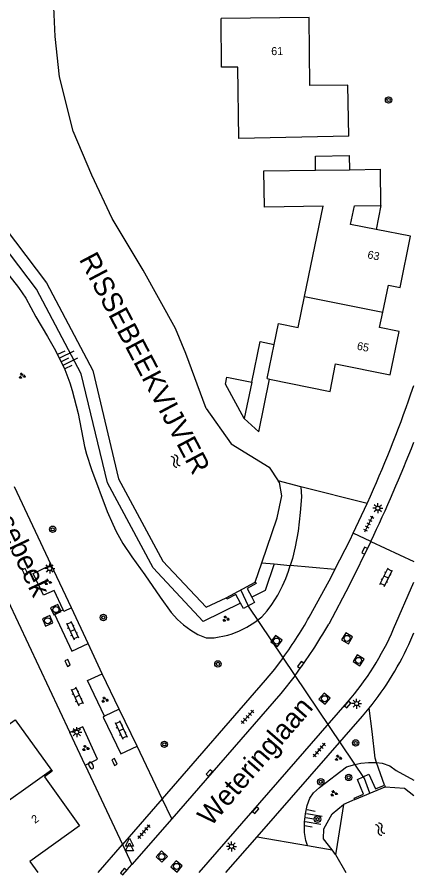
# Model space of a CAD drawing. Extents: x 128999 to 131010, y 395498 to 399007.
# Drawn here: x 130950.5 to 131000, y 395499.7 to 395606.9 of the extents above; entities that cross this region are included whole.
import ezdxf

# ---------------------------------------------------------------- set-up
doc = ezdxf.new("R2010")
doc.units = 0
for name, color, linetype in [('gg-afsc-erfafscheiding', 7, 'Continuous'), ('gg-anno-huisnummerreeks BGT', 7, 'Continuous'), ('gg-anno-naam water', 7, 'Continuous'), ('gg-anno-openbare ruimte label', 7, 'Continuous'), ('gg-bbg-gedigitaliseerde bebouwing', 7, 'Continuous'), ('gg-bbg-gedigitaliseerde bijgebouw', 7, 'Continuous'), ('gg-bbg-hoofdgebouw', 7, 'Continuous'), ('gg-bbg-luifel en loopbrug', 7, 'Continuous'), ('gg-bbg-tussenscheiding', 7, 'Continuous'), ('gg-knt-BGT kruinlijn', 7, 'Continuous'), ('gg-knt-verharding', 7, 'Continuous'), ('gg-knt-verharding nz', 7, 'Continuous'), ('gg-kntw-beschoeiing', 7, 'Continuous'), ('gg-kwrk-duiker nz buis', 7, 'Continuous'), ('gg-kwrk-uitstroombak niveau min 01', 7, 'Continuous'), ('gt-grn-groengrens', 7, 'Continuous'), ('gt-grn-vlakafsluiter', 7, 'Continuous'), ('gt-grn-weggrens', 7, 'Continuous'), ('gt-symb-boom', 7, 'Continuous'), ('gt-symb-brandkraan', 7, 'Continuous'), ('gt-symb-groenvak', 7, 'Continuous'), ('gt-symb-klinker verharding', 7, 'Continuous'), ('gt-symb-kolk', 7, 'Continuous'), ('gt-symb-lichtmast', 7, 'Continuous'), ('gt-symb-rioolschacht', 7, 'Continuous'), ('gt-symb-talud symbool', 7, 'Continuous'), ('gt-symb-tegel verharding', 7, 'Continuous'), ('gt-symb-waterafsluiter', 7, 'Continuous'), ('gt-symb-watersymbool', 7, 'Continuous')]:
    doc.layers.add(name, color=color, linetype=linetype)

# ---------------------------------------------------------------- blocks, each defined once
blk = doc.blocks.new('gt0-KL1')
at = {"layer": 'gt-symb-klinker verharding'}
for p, q in [((-1.15, 0.3), (1.15, 0.3)), ((-1, -0.3), (-1, 0.3)), ((-0.5, 0.3), (-0.5, 0.45)), ((0, -0.3), (0, 0.3)), ((0.5, 0.3), (0.5, 0.45)), ((1, -0.3), (1, 0.3)), ((-1.15, -0.3), (1.15, -0.3)), ((-0.5, -0.45), (-0.5, -0.3)), ((0.5, -0.45), (0.5, -0.3))]:
    blk.add_line(p, q, dxfattribs=at)
blk = doc.blocks.new('gt0-KOLK')
at = {"layer": 'gt-symb-kolk'}
blk.add_lwpolyline([(0, 0), (0.38, 0), (0.38, 0.4), (-0.38, 0.4), (-0.38, 0), (0, 0)], dxfattribs=at)
blk = doc.blocks.new('gt0-TEG1')
at = {"layer": 'gt-symb-tegel verharding'}
for p, q in [((-1.12, 0), (1.12, 0)), ((-0.9, -0.25), (-0.9, 0.25)), ((-0.45, -0.25), (-0.45, 0.25)), ((0, -0.25), (0, 0.25)), ((0.45, -0.25), (0.45, 0.25)), ((0.9, -0.25), (0.9, 0.25))]:
    blk.add_line(p, q, dxfattribs=at)
blk = doc.blocks.new('gt0-LMAST')
at = {"layer": 'gt-symb-lichtmast'}
for p, q in [((-0.18, 0.17), (-0.45, 0.44)), ((-0.01, 0.25), (-0.01, 0.62)), ((0.17, 0.17), (0.44, 0.44)), ((-0.26, 0), (-0.63, 0)), ((-0.18, -0.18), (-0.45, -0.45)), ((-0.01, -0.25), (-0.01, -0.63)), ((0.44, -0.45), (0.17, -0.18)), ((0.24, 0), (0.62, 0))]:
    blk.add_line(p, q, dxfattribs=at)
blk.add_circle((-0.01, 0), 0.25, dxfattribs=at)
blk = doc.blocks.new('gt0-RS')
at = {"layer": 'gt-symb-rioolschacht'}
blk.add_lwpolyline([(-0.5, -0.5), (0.5, -0.5), (0.5, 0.5), (-0.5, 0.5)], close=True, dxfattribs=at)
blk.add_circle((0, 0), 0.375, dxfattribs=at)
blk = doc.blocks.new('gt0-BOOM')
at = {"layer": 'gt-symb-boom'}
for radius in [0.4, 0.2]:
    blk.add_circle((0, 0), radius, dxfattribs=at)
blk = doc.blocks.new('gt0-GRVAK')
at = {"layer": 'gt-symb-groenvak'}
for p, q in [((-0.11, 0.19), (-0.23, 0.24)), ((-0.18, 0.15), (0.09, 0.15)), ((-0.09, 0.21), (-0.16, 0.32)), ((-0.05, 0.21), (-0.05, 0.39)), ((0, 0.21), (0.06, 0.32)), ((0.01, 0.19), (0.13, 0.24)), ((0.26, -0.05), (0.2, 0.06)), ((0.31, -0.05), (0.31, 0.13)), ((0.35, -0.05), (0.41, 0.06)), ((-0.24, -0.23), (-0.36, -0.18)), ((-0.32, -0.26), (-0.05, -0.26)), ((-0.23, -0.21), (-0.29, -0.1)), ((-0.18, -0.2), (-0.18, -0.02)), ((-0.14, -0.21), (-0.07, -0.1)), ((-0.12, -0.23), (0, -0.18)), ((0.24, -0.07), (0.12, -0.02)), ((0.17, -0.11), (0.44, -0.11)), ((0.37, -0.07), (0.49, -0.02))]:
    blk.add_line(p, q, dxfattribs=at)
blk = doc.blocks.new('gt0-WA')
at = {"layer": 'gt-symb-watersymbool'}
for centre, start, end in [((-0.32, 0.02), 28.0725, 151.9275), ((0.43, 0.42), 208.0725, 331.9275), ((-0.32, -0.43), 28.0725, 151.9275), ((0.43, -0.03), 208.0725, 331.9275)]:
    blk.add_arc(centre, 0.425, start, end, dxfattribs=at)
blk = doc.blocks.new('gt0-TALUD_1')
at = {"layer": 'gt-symb-talud symbool'}
for p, q in [((-1, -1), (-1, 0)), ((-0.5, -2), (-0.5, 0)), ((0, -1), (0, 0)), ((0.5, -2), (0.5, 0)), ((1, -1), (1, 0))]:
    blk.add_line(p, q, dxfattribs=at)
blk = doc.blocks.new('gt0-WAFSL')
at = {"layer": 'gt-symb-waterafsluiter'}
for p, q in [((-0.5, -0.33), (0, 0.67)), ((0, 0.67), (0.5, -0.33)), ((0.5, -0.33), (-0.5, -0.33))]:
    blk.add_line(p, q, dxfattribs=at)
blk = doc.blocks.new('gt0-BR')
at = {"layer": 'gt-symb-brandkraan'}
for centre, radius, start, end in [((-0.24, 0), 0.206, 107.5669, 252.4331), ((0.6, -2.66), 3, 106.892, 107.5669), ((0, -0.69), 0.938, 73.108, 106.892), ((-0.6, -2.66), 3, 72.4331, 73.108), ((0.24, 0), 0.206, 287.567, 72.4331), ((0.6, 2.66), 3, 252.4331, 253.108), ((0, 0.69), 0.938, 253.108, 286.8921), ((-0.6, 2.66), 3, 286.8921, 287.567)]:
    blk.add_arc(centre, radius, start, end, dxfattribs=at)

msp = doc.modelspace()

# ---------------------------------------------------------------- linework, layer by layer
at = {"layer": 'gg-afsc-erfafscheiding'}
for p, q in [((130985.92, 395548.21), (130983.09, 395548.94)), ((130994.16, 395546.1), (130985.92, 395548.21)), ((130996.35, 395510.91), (130995.36, 395513.76))]:
    msp.add_line(p, q, dxfattribs=at)
msp.add_lwpolyline([(130995.36, 395513.76), (130995.18, 395514.28), (130994.82, 395517.61)], dxfattribs=at)
at = {"layer": 'gg-bbg-gedigitaliseerde bebouwing'}
for p, q in [((130987.74, 395587.75), (130991.96, 395587.81)), ((130991.96, 395587.81), (130995.84, 395587.86)), ((130981.69, 395561.71), (130982.58, 395565.98))]:
    msp.add_line(p, q, dxfattribs=at)
for points in [[(130991.88, 395592), (130978.16, 395591.72), (130978.05, 395600.63), (130976.02, 395600.63), (130975.95, 395606.68)], [(130986.37, 395571.96), (130988.67, 395583.24), (130981.35, 395583.14), (130981.29, 395587.66), (130987.74, 395587.75)], [(130982.58, 395565.98), (130983.12, 395568.59), (130985.58, 395568.09), (130986.37, 395571.96)]]:
    msp.add_lwpolyline(points, dxfattribs=at)
at = {"layer": 'gg-bbg-gedigitaliseerde bijgebouw'}
for p, q in [((130978.85, 395556.73), (130976.48, 395561)), ((130979.77, 395561.26), (130978.85, 395556.73))]:
    msp.add_line(p, q, dxfattribs=at)
msp.add_lwpolyline([(130976.48, 395561), (130976.66, 395561.9), (130979.77, 395561.26)], dxfattribs=at)
at = {"layer": 'gg-bbg-hoofdgebouw'}
for p, q in [((130995.9, 395583.35), (130995.84, 395587.86)), ((130981.69, 395561.71), (130982, 395561.64)), ((130982, 395561.64), (130989.55, 395560.1)), ((130952.08, 395501.38), (130953.07, 395500))]:
    msp.add_line(p, q, dxfattribs=at)
for points in [[(130991.88, 395592), (130991.78, 395598.38), (130987.03, 395598.33), (130986.95, 395606.81), (130975.95, 395606.68)], [(130995.3, 395580.34), (130992.09, 395580.97), (130992.58, 395583.3), (130995.9, 395583.35)], [(130996.13, 395570.02), (130996.85, 395573.37), (130998.28, 395573.11), (130999.59, 395579.49), (130995.3, 395580.34)], [(130989.55, 395560.1), (130990.24, 395563.54), (130997.06, 395562.17), (130998.18, 395567.6), (130995.72, 395568.08), (130996.13, 395570.02)], [(130942.74, 395521.1), (130946.22, 395516.22), (130950.26, 395519.1), (130954.79, 395512.79)], [(130954.79, 395512.79), (130954.86, 395512.68), (130953.9, 395511.98), (130958.29, 395505.84), (130952.08, 395501.38)]]:
    msp.add_lwpolyline(points, dxfattribs=at)
at = {"layer": 'gg-bbg-luifel en loopbrug'}
msp.add_line((130995.9, 395583.35), (130995.3, 395580.34), dxfattribs=at)
for points in [[(130987.74, 395587.75), (130987.71, 395589.5), (130991.93, 395589.59), (130991.96, 395587.81)], [(130979.77, 395561.26), (130980.81, 395566.34), (130982.58, 395565.98)], [(130978.85, 395556.73), (130980.65, 395555.07), (130982, 395561.64)]]:
    msp.add_lwpolyline(points, dxfattribs=at)
at = {"layer": 'gg-bbg-tussenscheiding'}
msp.add_line((130986.37, 395571.96), (130996.13, 395570.02), dxfattribs=at)
msp.add_lwpolyline([(130954.79, 395512.79), (130946.49, 395506.89), (130946.39, 395507.02)], dxfattribs=at)
at = {"layer": 'gg-knt-BGT kruinlijn'}
msp.add_line((130997.81, 395512.75), (131000, 395511.53), dxfattribs=at)
for points in [[(130948.57, 395575.78), (130950.68, 395573.11), (130951.58, 395571.75), (130952.85, 395569.42), (130954.3, 395566.98), (130955.27, 395565.23), (130956.45, 395562.85), (130957.07, 395561.2), (130957.36, 395560.24), (130958.11, 395557.36), (130958.92, 395553.25), (130959.17, 395552.28), (130959.76, 395550.37), (130961.75, 395545.12), (130962.43, 395543.51), (130962.86, 395542.61), (130963.69, 395541.12), (130964.81, 395539.43), (130966.42, 395537.21), (130968.33, 395534.41), (130969.74, 395532.49), (130970.52, 395531.6), (130971.28, 395530.95), (130972.19, 395530.3), (130973.05, 395529.74), (130974.08, 395529.34), (130975.07, 395529.35), (130976.78, 395529.67), (130977.34, 395529.82), (130978.26, 395530.19), (130979.15, 395530.66), (130980.18, 395531.29), (130981.03, 395531.97), (130981.71, 395532.7), (130982.3, 395533.51), (130983.02, 395534.66), (130983.62, 395535.82), (130984.03, 395536.73), (130984.38, 395537.67), (130984.59, 395538.38)], [(130985.92, 395548.21), (130985.98, 395546.96), (130985.83, 395544.97), (130985.57, 395542.64), (130985.18, 395540.68), (130984.85, 395539.24), (130984.59, 395538.38)], [(130986.73, 395503.37), (130986.52, 395504.03), (130986.35, 395505.02), (130986.36, 395506.33), (130986.47, 395507.33), (130986.67, 395508.37), (130987.01, 395509.29), (130987.48, 395509.95), (130988.21, 395510.63), (130991.58, 395513.21), (130992.64, 395513.52), (130993.4, 395513.68), (130994.33, 395513.77), (130995.36, 395513.76)], [(130995.36, 395513.76), (130996.06, 395513.68), (130997.02, 395513.36), (130997.81, 395512.75)]]:
    msp.add_lwpolyline(points, dxfattribs=at)
at = {"layer": 'gg-knt-verharding'}
for p, q in [((130999.64, 395559.81), (131000, 395560.85)), ((130954.76, 395538.45), (130950.19, 395548.21)), ((130992.43, 395542.41), (130994.16, 395546.1)), ((130994.16, 395546.1), (130994.22, 395546.21)), ((130946.11, 395540.8), (130957.09, 395517.49)), ((130957.27, 395533.08), (130954.76, 395538.45)), ((130997.47, 395530.45), (131000, 395536.3)), ((130959.35, 395528.63), (130957.27, 395533.08)), ((130999.61, 395529.07), (131000, 395529.96)), ((130961.13, 395524.83), (130959.35, 395528.63)), ((130963.25, 395520.4), (130961.13, 395524.83)), ((130973.23, 395500), (130991.73, 395521.3)), ((130963.25, 395520.4), (130961.42, 395519.55)), ((130965.46, 395515.79), (130963.25, 395520.4)), ((130959.01, 395513.41), (130957.09, 395517.49)), ((130968.61, 395509.21), (130965.46, 395515.79)), ((130959.01, 395513.41), (130963.66, 395503.52)), ((130968.61, 395509.21), (130963.66, 395503.52)), ((130969.8, 395506.73), (130964.83, 395501.02)), ((130976.53, 395500), (130980.45, 395504.49)), ((130960.6, 395500), (130963.66, 395503.52)), ((130963.95, 395500), (130964.83, 395501.02))]:
    msp.add_line(p, q, dxfattribs=at)
for points in [[(130990.16, 395537.87), (130992.04, 395541.57), (130992.43, 395542.41)], [(130994.63, 395541.38), (130991.92, 395535.87), (130989.38, 395531.04)], [(130956.23, 395532.82), (130955.11, 395535.23), (130953.81, 395534.68), (130952.52, 395537.37), (130954.76, 395538.45)], [(130987.15, 395532.28), (130989.67, 395536.89), (130990.16, 395537.87)], [(130957.27, 395533.08), (130956.32, 395532.64), (130956.23, 395532.82)], [(130983.69, 395526.86), (130982.6, 395525.43), (130981.46, 395524.03), (130968.61, 395509.21)], [(130961.42, 395519.55), (130959.3, 395523.99), (130961.13, 395524.83)], [(130985.18, 395524.64), (130983.41, 395522.39), (130969.8, 395506.73)], [(130980.45, 395504.49), (130993.59, 395519.53), (130994.41, 395520.53)], [(130959.01, 395513.41), (130960.54, 395514.19), (130958.69, 395518.22), (130957.09, 395517.49)]]:
    msp.add_lwpolyline(points, dxfattribs=at)
for centre, radius, start, end in [((130841.39, 395615.05), 167.62, 335.7511, 340.758), ((130811.55, 395628.08), 202.58, 334.6607, 338.4782), ((130943.35, 395556.39), 49.99, 323.7886, 331.1679), ((130936.06, 395561.44), 61.38, 323.1608, 330.314), ((130965.19, 395544.35), 35.15, 319.0242, 336.6927), ((130966.09, 395543.65), 36.56, 320.7712, 336.4979)]:
    msp.add_arc(centre, radius, start, end, dxfattribs=at)
at = {"layer": 'gg-knt-verharding nz'}
for points in [[(130956.23, 395532.82), (130955.17, 395532.29), (130957.34, 395527.68), (130959.35, 395528.63)], [(130961.42, 395519.55), (130961.24, 395519.44), (130963.42, 395514.83), (130965.46, 395515.79)]]:
    msp.add_lwpolyline(points, dxfattribs=at)
at = {"layer": 'gg-kntw-beschoeiing'}
for p, q in [((130980.22, 395536.29), (130981.03, 395538.7)), ((130991.22, 395508.49), (130990.31, 395502.74)), ((130992.63, 395509.12), (130991.22, 395508.49)), ((130990.31, 395502.74), (130990.23, 395502.26)), ((130990.23, 395502.26), (130991.52, 395500))]:
    msp.add_line(p, q, dxfattribs=at)
for points in [[(130974.1, 395557.99), (130971.56, 395564.84), (130970.28, 395567.97), (130966.22, 395575.24), (130962.34, 395581.72), (130959.84, 395587.12), (130957.51, 395592.64), (130955.8, 395599.42), (130955.24, 395604.44), (130955.01, 395609.98), (130955.07, 395610.41)], [(130947.69, 395582.22), (130954.18, 395573.66), (130959.96, 395562.73), (130963.14, 395549.2), (130968.68, 395538.91), (130974.08, 395533.16), (130976.58, 395534.34)], [(130974.1, 395557.99), (130977.22, 395553.56), (130981.93, 395550.67), (130983.09, 395548.94)], [(130981.03, 395538.7), (130982.94, 395544.34), (130983.53, 395547.07), (130983.23, 395548.74), (130983.09, 395548.94)], [(130996.42, 395510.73), (130998.83, 395510.55), (131000, 395509.65)]]:
    msp.add_lwpolyline(points, dxfattribs=at)
at = {"layer": 'gg-kwrk-duiker nz buis'}
msp.add_lwpolyline([(130994.52, 395509.93), (130993.83, 395511.76), (130979.38, 395533.27), (130978.4, 395535.31)], dxfattribs=at)
at = {"layer": 'gg-kwrk-uitstroombak niveau min 01'}
for p, q in [((130976.58, 395534.34), (130980.22, 395536.29)), ((130992.63, 395509.12), (130996.42, 395510.73)), ((130996.35, 395510.91), (130996.42, 395510.73))]:
    msp.add_line(p, q, dxfattribs=at)
for points in [[(130980.22, 395536.29), (130980.34, 395536.11), (130979.21, 395535.48), (130979.77, 395534.39)], [(130978.36, 395533.68), (130977.78, 395534.75), (130976.67, 395534.18), (130976.58, 395534.34)], [(130979.77, 395534.39), (130980.12, 395533.73), (130978.74, 395533), (130978.36, 395533.68)], [(130992.63, 395509.12), (130992.57, 395509.32), (130993.71, 395509.8), (130992.98, 395511.65), (130994.38, 395512.3), (130995.2, 395510.45), (130996.35, 395510.91)]]:
    msp.add_lwpolyline(points, dxfattribs=at)
at = {"layer": 'gt-grn-groengrens'}
for p, q in [((130981.03, 395538.7), (130982.57, 395538.56)), ((130982.57, 395538.56), (130984.59, 395538.38)), ((130990.16, 395537.87), (130984.59, 395538.38)), ((130990.23, 395502.26), (130989.79, 395502.83))]:
    msp.add_line(p, q, dxfattribs=at)
for points in [[(130978.36, 395533.68), (130973.73, 395531.35), (130967.46, 395538.06), (130961.76, 395548.7), (130958.51, 395562.3), (130952.91, 395572.89), (130946.4, 395581.47), (130944.89, 395584.21), (130942.44, 395590.05), (130939.91, 395597.3), (130938.71, 395603.36), (130938.67, 395611.55), (130939.67, 395616.57), (130941.51, 395620.71), (130944.03, 395624.39), (130949.29, 395629.39), (130952.35, 395631.22), (130957.5, 395633.24), (130961.34, 395633.73), (130967.63, 395633.8)], [(130982.57, 395538.56), (130981.43, 395535.23), (130979.77, 395534.39)], [(130989.79, 395502.83), (130988.73, 395504.2), (130988.77, 395505.48), (130989.82, 395507.34), (130991.22, 395508.49)]]:
    msp.add_lwpolyline(points, dxfattribs=at)
at = {"layer": 'gt-grn-vlakafsluiter'}
for p, q in [((130994.82, 395517.61), (130994.41, 395520.53)), ((130980.45, 395504.49), (130986.73, 395503.37)), ((130986.73, 395503.37), (130989.79, 395502.83))]:
    msp.add_line(p, q, dxfattribs=at)
at = {"layer": 'gt-grn-weggrens'}
for p, q in [((130994.63, 395541.38), (130992.43, 395542.41)), ((130994.63, 395541.38), (131000, 395538.86)), ((130969.8, 395506.73), (130968.61, 395509.21)), ((130963.66, 395503.52), (130964.83, 395501.02))]:
    msp.add_line(p, q, dxfattribs=at)

# ---------------------------------------------------------------- block references
at = {"layer": 'gt-symb-boom'}
for p in [(130996.85, 395596.52), (130954.93, 395542.89), (130961.26, 395531.87), (130975.55, 395526.07), (130968.87, 395516.03), (130992.74, 395516.2), (130988.39, 395511.34), (130991.87, 395511.89), (130987.98, 395506.68)]:
    msp.add_blockref('gt0-BOOM', p, dxfattribs=at)
at = {"layer": 'gt-symb-brandkraan', "rotation": -63.69130406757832}
msp.add_blockref('gt0-BR', (130959.73, 395513.4), dxfattribs=at)
at = {"layer": 'gt-symb-groenvak'}
for p in [(130951.11, 395562.05), (130954.32, 395536.29), (130976.53, 395531.7), (130961.43, 395521.59), (130959.03, 395515.55), (130990.56, 395514.33), (130990.01, 395509.89)]:
    msp.add_blockref('gt0-GRVAK', p, dxfattribs=at)
at = {"layer": 'gt-symb-klinker verharding'}
for p, rotation in [((130996.55, 395536.9), 63.89617500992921), ((130957.4, 395530.25), -65.4849292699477), ((130957.99, 395522.02), -64.79277878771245), ((130963.48, 395517.83), -65.4849292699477)]:
    msp.add_blockref('gt0-KL1', p, dxfattribs=dict(at, rotation=rotation))
at = {"layer": 'gt-symb-kolk'}
for p, rotation in [((130994.04, 395540.13), 64.28048704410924), ((130951.31, 395537.48), -64.79277878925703), ((130956.61, 395526.11), -64.79277878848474), ((130986.05, 395525.84), 54.40236850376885), ((130991.58, 395521.13), -130.61993954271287), ((130962.47, 395513.74), -64.79277878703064), ((130974.63, 395512.3), 48.60919760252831), ((130980.12, 395507.93), -130.6634038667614), ((130963.94, 395500), 48.30011277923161)]:
    msp.add_blockref('gt0-KOLK', p, dxfattribs=dict(at, rotation=rotation))
at = {"layer": 'gt-symb-lichtmast'}
for p in [(130995.52, 395545.52), (130954.57, 395537.99), (130992.87, 395521.11), (130957.95, 395517.54), (130977.26, 395503.28)]:
    msp.add_blockref('gt0-LMAST', p, dxfattribs=at)
at = {"layer": 'gt-symb-rioolschacht'}
for p, rotation in [((130955.34, 395532.85), 24.97533465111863), ((130954.31, 395531.46), -65.92116276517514), ((130991.68, 395529.26), 59.58676936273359), ((130982.87, 395528.93), -35.18453930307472), ((130993.1, 395526.51), 57.788102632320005), ((130988.87, 395521.73), 49.01346679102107), ((130968.55, 395502), 46.21542824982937), ((130970.4, 395500.78), -40.98653320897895)]:
    msp.add_blockref('gt0-RS', p, dxfattribs=dict(at, rotation=rotation))
at = {"layer": 'gt-symb-talud symbool'}
for p, xscale, yscale, rotation in [((130956, 395563.81), 0.9999704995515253, 0.9999704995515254, 116.48817853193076), ((130986.52, 395506.84), 0.999562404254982, 0.999562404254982, 80.20785375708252)]:
    msp.add_blockref('gt0-TALUD_1', p, dxfattribs=dict(at, xscale=xscale, yscale=yscale, rotation=rotation))
at = {"layer": 'gt-symb-tegel verharding'}
for p, rotation in [((130994.39, 395543.56), 63.07637464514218), ((130979.25, 395519.46), -130.9057260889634), ((130988.22, 395515.32), 49.01346679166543), ((130966.33, 395505.11), 48.97586595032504)]:
    msp.add_blockref('gt0-TEG1', p, dxfattribs=dict(at, rotation=rotation))
at = {"layer": 'gt-symb-waterafsluiter'}
for p in [(130964.52, 395503.63), (130964.51, 395503.07)]:
    msp.add_blockref('gt0-WAFSL', p, dxfattribs=at)
at = {"layer": 'gt-symb-watersymbool'}
for p, rotation in [((130970.26, 395551.46), -61.76909817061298), ((130995.77, 395505.49), -58.86920085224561)]:
    msp.add_blockref('gt0-WA', p, dxfattribs=dict(at, rotation=rotation))

# ---------------------------------------------------------------- texts
at = {"layer": 'gg-anno-huisnummerreeks BGT'}
for s, rotation, p in [('61', 0.5, (130982.21, 395602.12)), ('63', 348.5, (130994.15, 395576.76)), ('65', 348.3, (130992.84, 395565.35)), ('2', 35.5, (130952.72, 395506.08))]:
    msp.add_text(s, height=1, rotation=rotation, dxfattribs=at).set_placement(p)
at = {"layer": 'gg-anno-naam water'}
msp.add_text('RISSEBEEKVIJVER', height=2.5, rotation=297.8199, dxfattribs=at).set_placement((130958.18, 395576.63))
at = {"layer": 'gg-anno-openbare ruimte label'}
for s, rotation, p in [('Rissebeek', 295.2, (130945.88, 395548.36)), ('Weteringlaan', 49.1, (130974.67, 395505.67))]:
    msp.add_text(s, height=2.5, rotation=rotation, dxfattribs=at).set_placement(p)

doc.saveas('drawing.dxf')
